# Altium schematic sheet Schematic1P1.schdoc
size 555 x 555 mm; Symbol: Drawing-Symbol_A4; Company: 嘉立创EDA; Version: V1.0; Page Size: A4; @Project Name: psone; @Update Date: 2026-04-22; @Create Date: 2026-04-22; Device: Drawing-Symbol_A4; @Board Name: Board1; @Page Name: P1; @Create Time: 20:13:25; @Page Count: 1; @Page No: 1; @Schematic Name: Schematic1; @Update Time: 20:13:25; @Assembly Variant: Basic; Border: 1; Title Block Position: 3; Size: A4; Width: 2185.03937007874; Height: 2185.03937007874; Region Start: 1; X Region Count: 6; Y Region Count: 4; Blade Width: 10
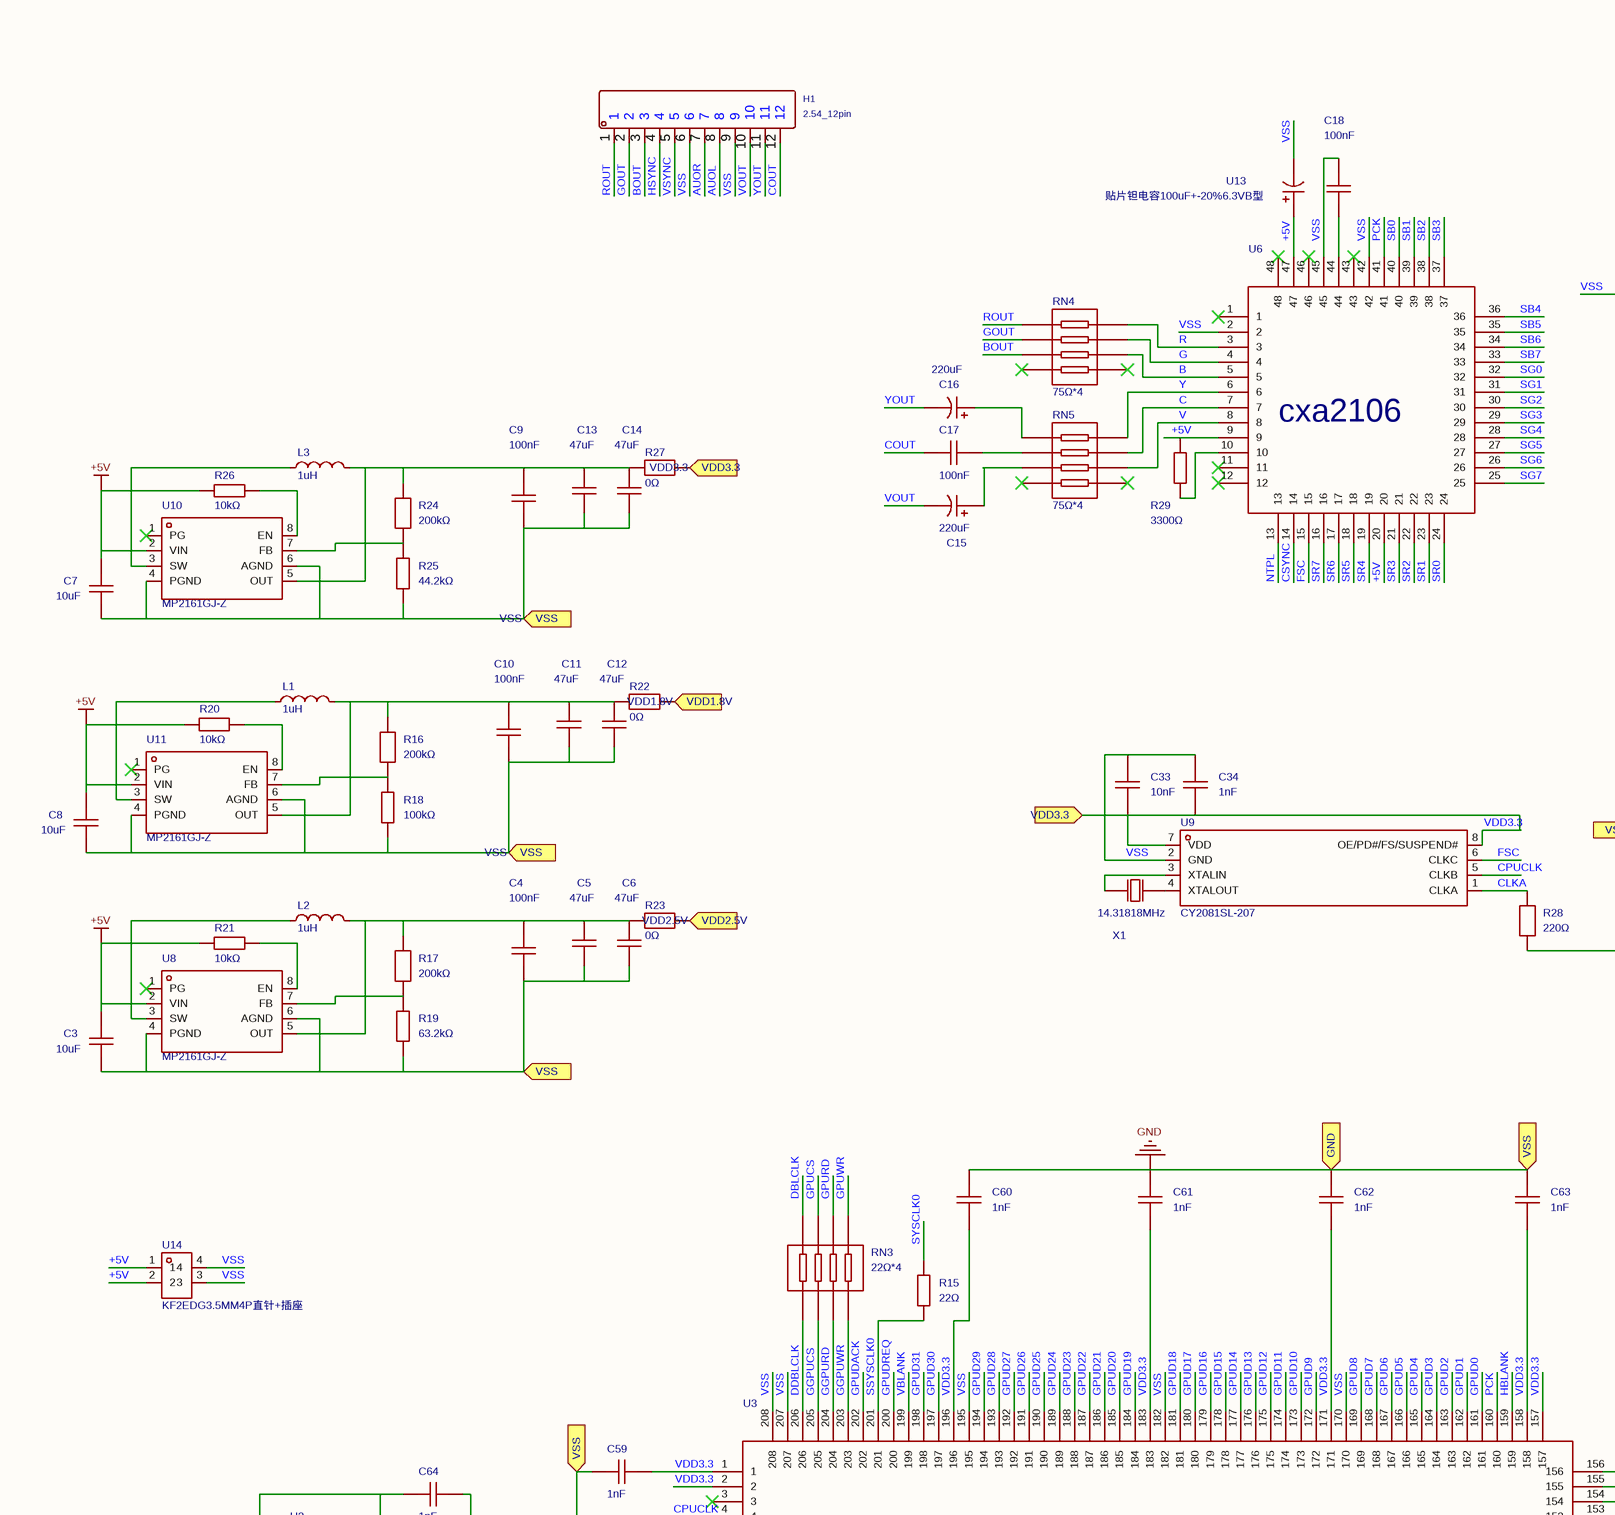
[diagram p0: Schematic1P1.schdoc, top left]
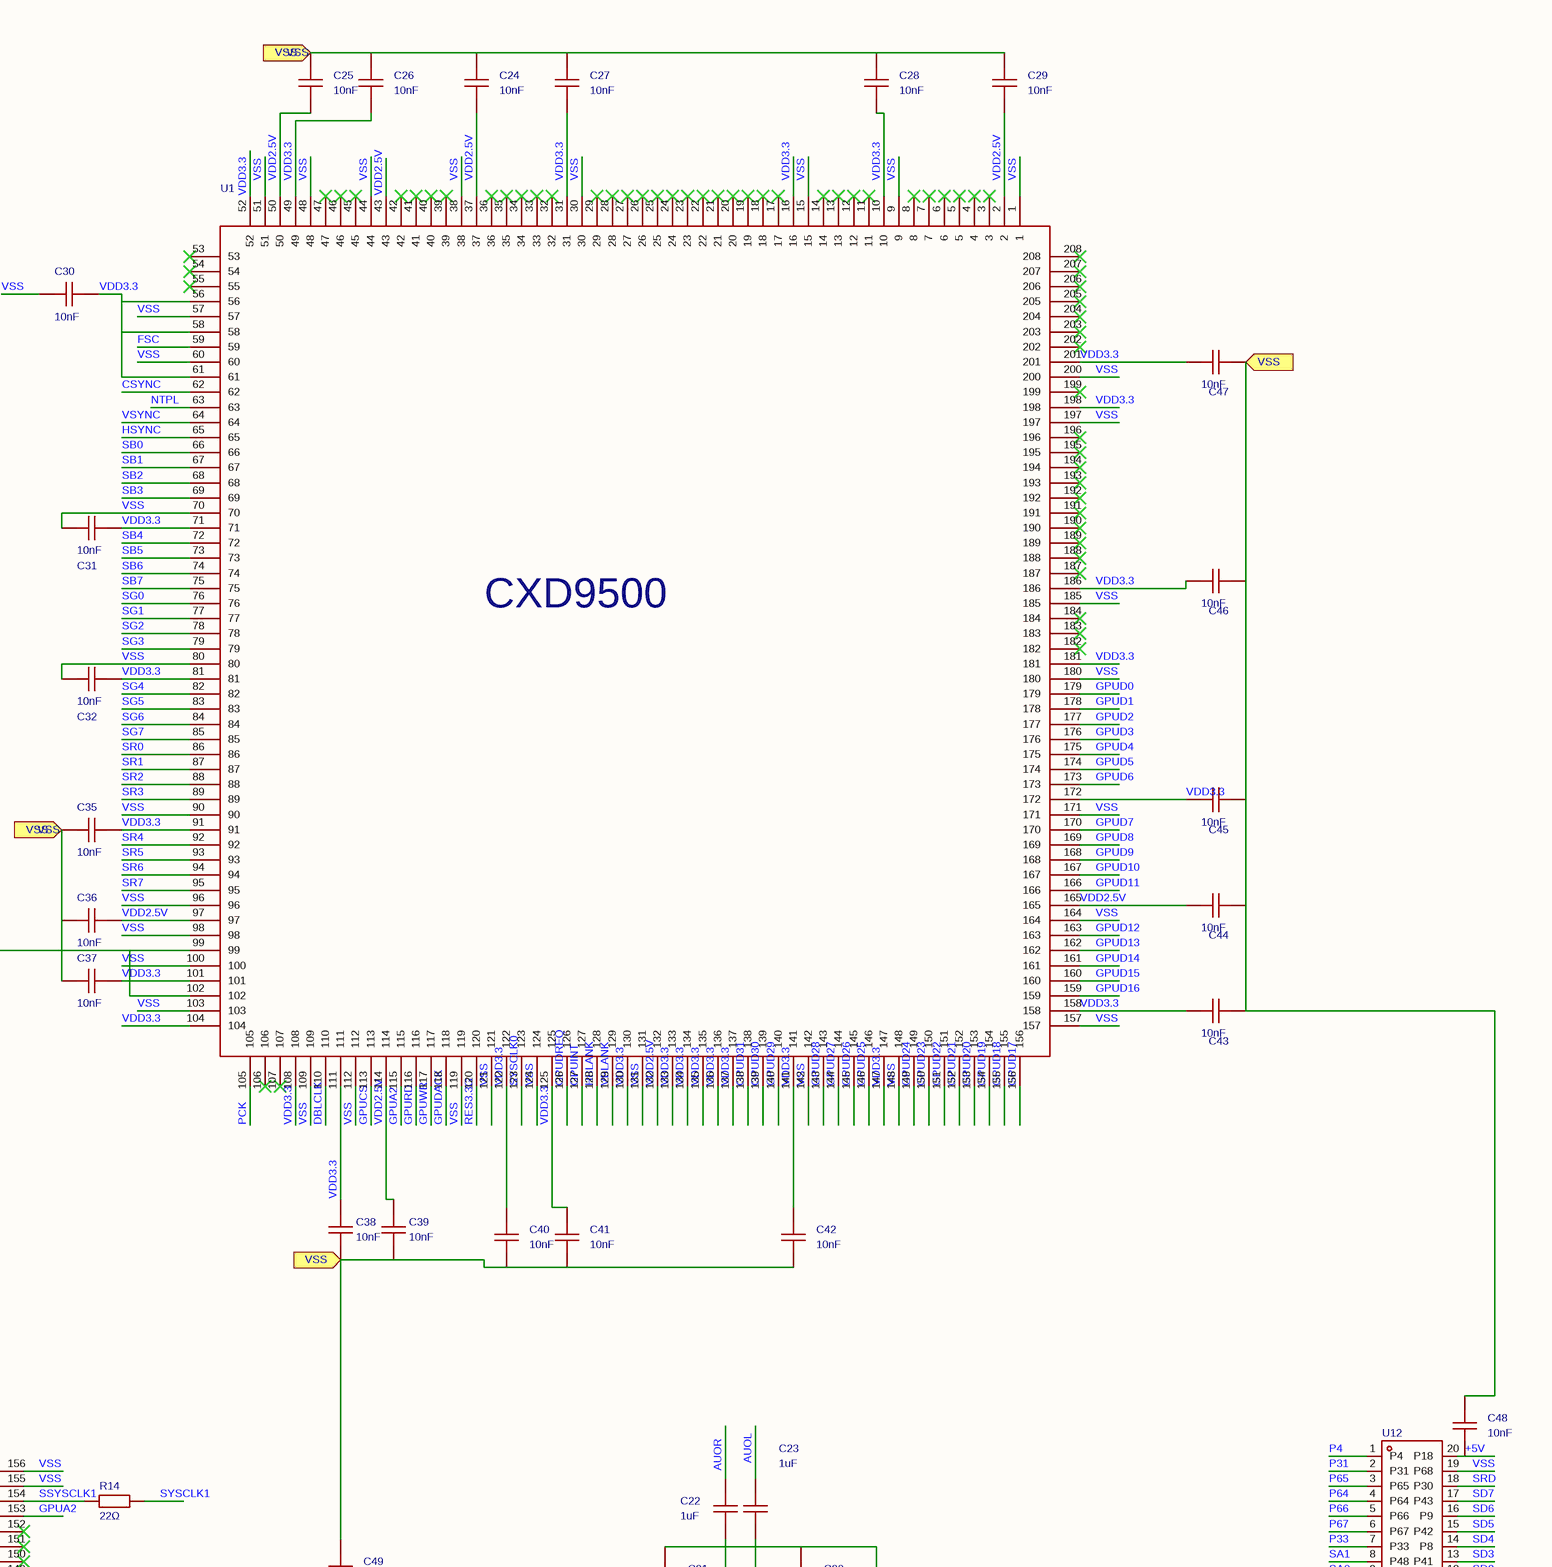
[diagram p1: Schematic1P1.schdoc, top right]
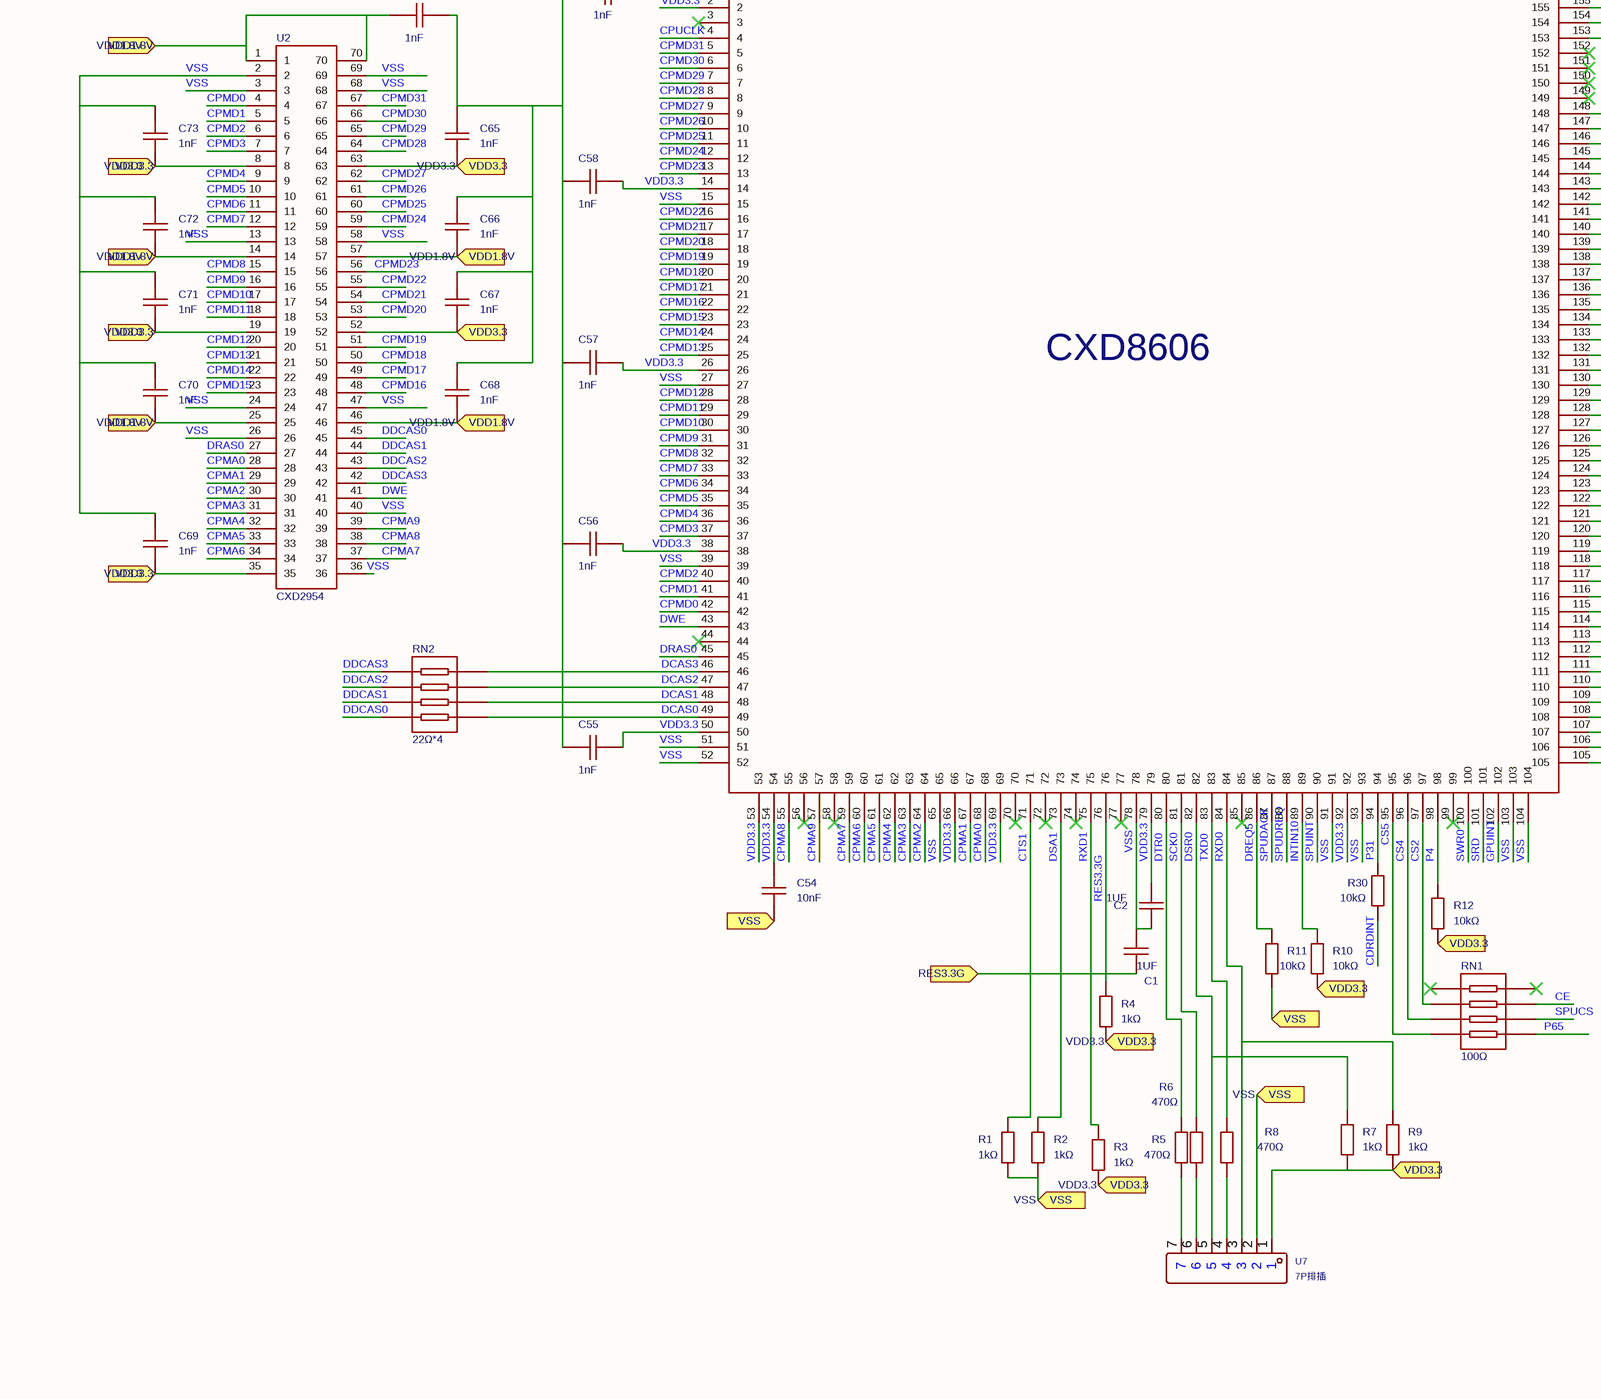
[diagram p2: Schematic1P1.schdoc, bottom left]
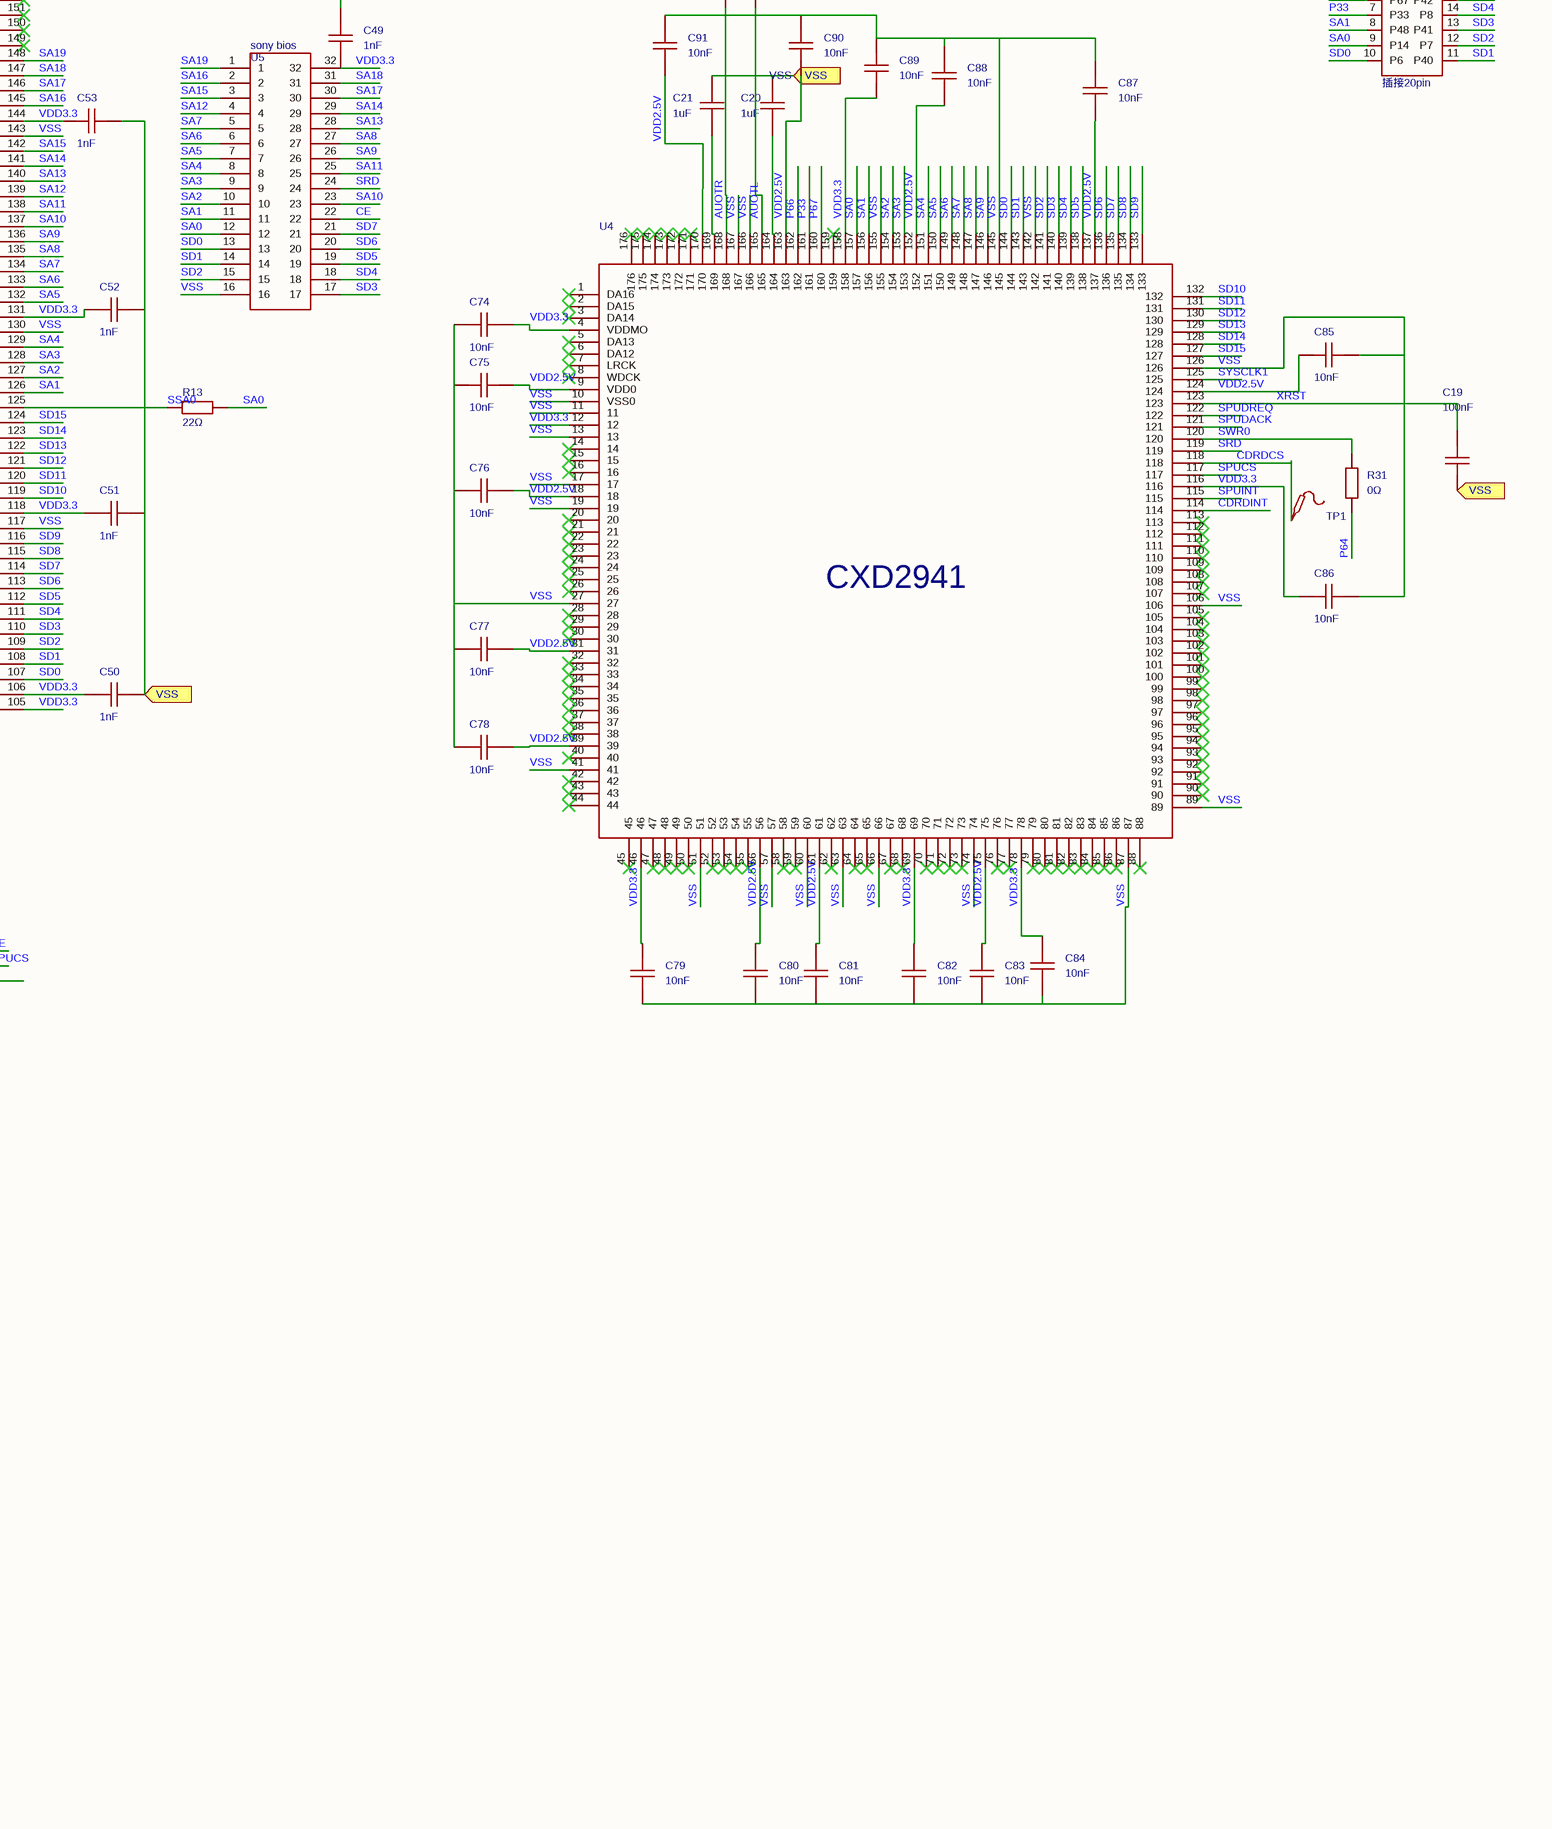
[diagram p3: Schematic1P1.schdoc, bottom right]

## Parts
C1  1UF  [C0603]
C2  1UF  [C0603]
C3  10uF  [C0603]
C4  100nF  [C0805]
C5  47uF  [C0805]
C6  47uF  [C0805]
C7  10uF  [C0603]
C8  10uF  [C0603]
C9  100nF  [C0805]
C10  100nF  [C0805]
C11  47uF  [C0805]
C12  47uF  [C0805]
C13  47uF  [C0805]
C14  47uF  [C0805]
C15  220uF  [CAP-SMD_L3.5-W2.8-R-RD]
C16  220uF  [CAP-SMD_L3.5-W2.8-R-RD]
C17  100nF  [C0805]
C18  100nF  [C0805]
C19  100nF  [C0805]
C20  1uF  [C0805]
C21  1uF  [C0805]
C22  1uF  [C0805]
C23  1uF  [C0805]
C24  10nF  [C0603]
C25  10nF  [C0603]
C26  10nF  [C0603]
C27  10nF  [C0603]
C28  10nF  [C0603]
C29  10nF  [C0603]
C30  10nF  [C0603]
C31  10nF  [C0603]
C32  10nF  [C0603]
C33  10nF  [C0603]
C34  1nF  [C0603]
C35  10nF  [C0603]
C36  10nF  [C0603]
C37  10nF  [C0603]
C38  10nF  [C0603]
C39  10nF  [C0603]
C40  10nF  [C0603]
C41  10nF  [C0603]
C42  10nF  [C0603]
C43  10nF  [C0603]
C44  10nF  [C0603]
C45  10nF  [C0603]
C46  10nF  [C0603]
C47  10nF  [C0603]
C48  10nF  [C0603]
C49  1nF  [C0603]
C50  1nF  [C0603]
C51  1nF  [C0603]
C52  1nF  [C0603]
C53  1nF  [C0603]
C54  10nF  [C0603]
C55  1nF  [C0603]
C56  1nF  [C0603]
C57  1nF  [C0603]
C58  1nF  [C0603]
C59  1nF  [C0603]
C60  1nF  [C0603]
C61  1nF  [C0603]
C62  1nF  [C0603]
C63  1nF  [C0603]
C64  1nF  [C0603]
C65  1nF  [C0603]
C66  1nF  [C0603]
C67  1nF  [C0603]
C68  1nF  [C0603]
C69  1nF  [C0603]
C70  1nF  [C0603]
C71  1nF  [C0603]
C72  1nF  [C0603]
C73  1nF  [C0603]
C74  10nF  [C0603]
C75  10nF  [C0603]
C76  10nF  [C0603]
C77  10nF  [C0603]
C78  10nF  [C0603]
C79  10nF  [C0603]
C80  10nF  [C0603]
C81  10nF  [C0603]
C82  10nF  [C0603]
C83  10nF  [C0603]
C84  10nF  [C0603]
C85  10nF  [C0603]
C86  10nF  [C0603]
C87  10nF  [C0603]
C88  10nF  [C0603]
C89  10nF  [C0603]
C90  10nF  [C0603]
C91  10nF  [C0603]
H1  2.54_12pin  [12PIN-P2.54]
L1  1uH  [IND-SMD_L3.0-W3.0_LPS3015-222ML]
L2  1uH  [IND-SMD_L3.0-W3.0_LPS3015-222ML]
L3  1uH  [IND-SMD_L3.0-W3.0_LPS3015-222ML]
R1  1kΩ  [R0603]
R2  1kΩ  [R0603]
R3  1kΩ  [R0603]
R4  1kΩ  [R0603]
R5  470Ω  [R0603]
R6  470Ω  [R0603]
R7  1kΩ  [R0603]
R8  470Ω  [R0603]
R9  1kΩ  [R0603]
R10  10kΩ  [R0603]
R11  10kΩ  [R0603]
R12  10kΩ  [R0603]
R13  22Ω  [R0603]
R14  22Ω  [R0603]
R15  22Ω  [R0603]
R16  200kΩ  [R0805]
R17  200kΩ  [R0805]
R18  100kΩ  [R0805]
R19  63.2kΩ  [R0805]
R20  10kΩ  [R0805]
R21  10kΩ  [R0805]
R22  0Ω  [R1206]
R23  0Ω  [R1206]
R24  200kΩ  [R0805]
R25  44.2kΩ  [R0805]
R26  10kΩ  [R0805]
R27  0Ω  [R1206]
R28  220Ω  [R0805]
R29  3300Ω  [R0603]
R30  10kΩ  [R0603]
R31  0Ω  [R0603]
RN1  100Ω  [RES-ARRAY-SMD_0603-8P-L3.2-W1.6-BL]
RN2  22Ω*4  [RES-ARRAY-SMD_0603-8P-L3.2-W1.6-BL]
RN3  22Ω*4  [RES-ARRAY-SMD_0603-8P-L3.2-W1.6-BL]
RN4  75Ω*4  [RES-ARRAY-SMD_0603-8P-L3.2-W1.6-BL]
RN5  75Ω*4  [RES-ARRAY-SMD_0603-8P-L3.2-W1.6-BL]
TP1  (no value)  [Test-Point-0.5mm]
U1  (no value)  [PQFP-208_L28.0-W28.0-P0.50-LS31.2-BL]
U2  CXD2954  [tssop-70]
U3  (no value)  [PQFP-208_L28.0-W28.0-P0.50-LS31.2-BL]
U4  (no value)  [LQFP-176_24.0X24.0X0.5P]
U5  (no value)  [628128SMD]
U6  (no value)  [ADV7123KSTZ50]
U7  7P排插  [7P排插]
U8  MP2161GJ-Z  [TSOT-23-8_L2.9-W1.6-P0.65-LS2.8-BR]
U9  CY2081SL-207  [SOIC-8_L4.9-W3.9-P1.27-LS6.0-BL]
U10  MP2161GJ-Z  [TSOT-23-8_L2.9-W1.6-P0.65-LS2.8-BR]
U11  MP2161GJ-Z  [TSOT-23-8_L2.9-W1.6-P0.65-LS2.8-BR]
U12  插接20pin  [20PIN-2.0MM_2_10]
U13  贴片钽电容100uF+-20%6.3VB型  [CAP-SMD_L3.5-W2.8-FD]
U14  KF2EDG3.5MM4P直针+插座  [CONN-TH_4P-P3.50_KF2EDGV-3.5-4P-1]
X1  14.31818MHz  [HC-49S_L11.4-W4.8-LS12.7]

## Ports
GND (in), RES3.3G (in), VDD1.8V (in), VDD2.5V (in), VDD3.3 (in), VSS (in)

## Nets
+5V: C3.2 C7.2 C8.2 C48.2 R20.2 R21.2 R26.2 R29.1 U6.9 U6.20 U6.47 U8.2(VIN) U10.2(VIN) U11.2(VIN) U12.20(P18) U13.1 U14.1 U14.2
VSS: C1.2 C2.1 C3.1 C4.1 C5.1 C6.1 C7.1 C8.1 C9.1 C10.1 C11.1 C12.1 C13.1 C14.1 C18.2 C19.1 C20.2 C21.2 C24.2 C25.2 C26.2 C27.2 C28.2 C29.2 C30.2 C31.2 C32.2 C33.2 C34.2 C35.2 C36.2 C37.2 C38.1 C39.1 C40.1 C41.1 C42.1 C43.1 C44.1 C45.1 C46.1 C47.1 C48.1 C49.2 C50.2 C51.2 C52.2 C53.2 C54.2 C55.1 C56.1 C57.1 C58.1 C59.1 C60.2 C61.2 C62.2 C63.2 C64.2 C65.2 C66.2 C67.2 C68.2 C69.2 C70.2 C71.2 C72.2 C73.2 C74.1 C75.1 C76.1 C77.1 C78.1 C79.1 C80.1 C81.1 C82.1 C83.1 C84.1 C85.1 C86.1 C87.1 C88.1 C89.1 C90.1 C91.1 H1.6 H1.9 R1.1 R2.1 R11.1 R18.1 R19.1 R25.1 U1.1 U1.9 U1.15 U1.30 U1.38 U1.44 U1.48 U1.51 U1.57 U1.60 U1.70 U1.80 U1.90 U1.96 U1.98 U1.100 U1.103 U1.109 U1.112 U1.119 U1.121 U1.124 U1.131 U1.142 U1.148 U1.157 U1.164 U1.171 U1.180 U1.185 U1.197 U1.200 U2.2 U2.3 U2.13 U2.24 U2.26 U2.36 U2.40 U2.47 U2.58 U2.68 U2.69 U3.15 U3.27 U3.39 U3.51 U3.52 U3.65 U3.78 U3.91 U3.93 U3.103 U3.104 U3.117 U3.130 U3.143 U3.155 U3.156 U3.170 U3.182 U3.195 U3.207 U3.208 U4.10(VSS0) U4.11 U4.13 U4.17 U4.19 U4.27 U4.41 U4.51 U4.57 U4.60 U4.63 U4.66 U4.74 U4.87 U4.89 U4.106 U4.126 U4.142 U4.145 U4.155 U4.166 U4.167 U5.16 U6.2 U6.42 U6.45 U7.2 U8.4(PGND) U8.6(AGND) U9.2(GND) U10.4(PGND) U10.6(AGND) U11.4(PGND) U11.6(AGND) U12.19(P68) U13.2 U14.3 U14.4 ; port VSS, port GND  [also labelled GND]
AUOL: C23.2 H1.8
AUOR: C22.2 H1.7
AUOTL: C23.1 U4.165
AUOTR: C22.1 U4.168
B: RN4.6 U6.5
BOUT: H1.3 RN4.3
C: RN5.7 U6.7
CDRDCS: TP1.1 U4.118
CDRDINT: R30.1 U4.114
CE: RN1.7 U5.22
CLKA: R28.2 U9.1(CLKA)
COUT: C17.2 H1.12
CPMA0: U2.28 U3.68
CPMA1: U2.29 U3.67
CPMA2: U2.30 U3.64
CPMA3: U2.31 U3.63
CPMA4: U2.32 U3.62
CPMA5: U2.33 U3.61
CPMA6: U2.34 U3.60
CPMA7: U2.37 U3.59
CPMA8: U2.38 U3.55
CPMA9: U2.39 U3.57
CPMD0: U2.4 U3.42
CPMD1: U2.5 U3.41
CPMD2: U2.6 U3.40
CPMD3: U2.7 U3.37
CPMD4: U2.9 U3.36
CPMD5: U2.10 U3.35
CPMD6: U2.11 U3.34
CPMD7: U2.12 U3.33
CPMD8: U2.15 U3.32
CPMD9: U2.16 U3.31
CPMD10: U2.17 U3.30
CPMD11: U2.18 U3.29
CPMD12: U2.20 U3.28
CPMD13: U2.21 U3.25
CPMD14: U2.22 U3.24
CPMD15: U2.23 U3.23
CPMD16: U2.48 U3.22
CPMD17: U2.49 U3.21
CPMD18: U2.50 U3.20
CPMD19: U2.51 U3.19
CPMD20: U2.53 U3.18
CPMD21: U2.54 U3.17
CPMD22: U2.55 U3.16
CPMD23: U2.56 U3.13
CPMD24: U2.59 U3.12
CPMD25: U2.60 U3.11
CPMD26: U2.61 U3.10
CPMD27: U2.62 U3.9
CPMD28: U2.64 U3.8
CPMD29: U2.65 U3.7
CPMD30: U2.66 U3.6
CPMD31: U2.67 U3.5
CPUCLK: U3.4 U9.5(CLKB)
CS2: RN1.2 U3.97
CS4: RN1.3 U3.96
CS5: RN1.4 U3.95
CSYNC: U1.62 U6.14
CTS1: R1.2 U3.71
DBLCLK: RN3.8 U1.110
DCAS0: RN2.5 U3.49
DCAS1: RN2.6 U3.48
DCAS2: RN2.7 U3.47
DCAS3: RN2.8 U3.46
DDBLCLK: RN3.1 U3.206
DDCAS0: RN2.4 U2.45
DDCAS1: RN2.3 U2.44
DDCAS2: RN2.2 U2.43
DDCAS3: RN2.1 U2.42
DRAS0: U2.27 U3.45
DREQ5: R11.2 U3.86
DSA1: R2.2 U3.73
DSR0: R7.2 U3.82 U7.5
DTR0: R5.2 U3.80
DWE: U2.41 U3.43
FSC: U1.59 U6.15 U9.6(CLKC)
G: RN4.7 U6.4
GGPUCS: RN3.2 U3.205
GGPURD: RN3.3 U3.204
GGPUWR: RN3.4 U3.203
GOUT: H1.2 RN4.2
GPUA2: U1.115 U3.153
GPUCS: RN3.7 U1.113
GPUD0: U1.179 U3.161
GPUD1: U1.178 U3.162
GPUD2: U1.177 U3.163
GPUD3: U1.176 U3.164
GPUD4: U1.175 U3.165
GPUD5: U1.174 U3.166
GPUD6: U1.173 U3.167
GPUD7: U1.170 U3.168
GPUD8: U1.169 U3.169
GPUD9: U1.168 U3.172
GPUD10: U1.167 U3.173
GPUD11: U1.166 U3.174
GPUD12: U1.163 U3.175
GPUD13: U1.162 U3.176
GPUD14: U1.161 U3.177
GPUD15: U1.160 U3.178
GPUD16: U1.159 U3.179
GPUD17: U1.156 U3.180
GPUD18: U1.155 U3.181
GPUD19: U1.154 U3.184
GPUD20: U1.153 U3.185
GPUD21: U1.152 U3.186
GPUD22: U1.151 U3.187
GPUD23: U1.150 U3.188
GPUD24: U1.149 U3.189
GPUD25: U1.146 U3.190
GPUD26: U1.145 U3.191
GPUD27: U1.144 U3.192
GPUD28: U1.143 U3.193
GPUD29: U1.140 U3.194
GPUD30: U1.139 U3.197
GPUD31: U1.138 U3.198
GPUDACK: U1.118 U3.202
GPUDREQ: U1.126 U3.200
GPUINT: U1.127 U3.102
GPURD: RN3.6 U1.116
GPUWR: RN3.5 U1.117
HBLANK: U1.128 U3.159
HSYNC: H1.4 U1.65
INTIN10: R10.2 U3.89
NTPL: U1.63 U6.13
P4: R12.2 U3.98 U12.1(P4)
P31: R30.2 U3.94 U12.2(P31)
P33: U4.161 U12.7(P33)
P64: R31.2 U12.4(P64)
P65: RN1.5 U12.3(P65)
P66: U4.162 U12.5(P66)
P67: U4.160 U12.6(P67)
PCK: U1.105 U3.160 U6.41
R: RN4.8 U6.3
RES3.3G: C1.1 R4.2 U1.120 U3.76 ; port RES3.3G
ROUT: H1.1 RN4.1
RXD0: R9.2 U3.84 U7.3
RXD1: R3.2 U3.75
SA0: R13.1 U4.157 U5.12 U12.9(P14)
SA1: U3.126 U4.156 U5.11 U12.8(P48)
SA2: U3.127 U4.154 U5.10
SA3: U3.128 U4.153 U5.9
SA4: U3.129 U4.151 U5.8
SA5: U3.132 U4.150 U5.7
SA6: U3.133 U4.149 U5.6
SA7: U3.134 U4.148 U5.5
SA8: U3.135 U4.147 U5.27
SA9: U3.136 U4.146 U5.26
SA10: U3.137 U5.23
SA11: U3.138 U5.25
SA12: U3.139 U5.4
SA13: U3.140 U5.28
SA14: U3.141 U5.29
SA15: U3.142 U5.3
SA16: U3.145 U5.2
SA17: U3.146 U5.30
SA18: U3.147 U5.31
SA19: U3.148 U5.1
SB0: U1.66 U6.40
SB1: U1.67 U6.39
SB2: U1.68 U6.38
SB3: U1.69 U6.37
SB4: U1.72 U6.36
SB5: U1.73 U6.35
SB6: U1.74 U6.34
SB7: U1.75 U6.33
SCK0: R6.2 U3.81
SD0: U3.107 U4.144 U5.13 U12.10(P6)
SD1: U3.108 U4.143 U5.14 U12.11(P40)
SD2: U3.109 U4.141 U5.15 U12.12(P7)
SD3: U3.110 U4.140 U5.17 U12.13(P41)
SD4: U3.111 U4.139 U5.18 U12.14(P8)
SD5: U3.112 U4.138 U5.19 U12.15(P42)
SD6: U3.113 U4.136 U5.20 U12.16(P9)
SD7: U3.114 U4.135 U5.21 U12.17(P43)
SD8: U3.115 U4.134
SD9: U3.116 U4.133
SD10: U3.119 U4.132
SD11: U3.120 U4.131
SD12: U3.121 U4.130
SD13: U3.122 U4.129
SD14: U3.123 U4.128
SD15: U3.124 U4.127
SG0: U1.76 U6.32
SG1: U1.77 U6.31
SG2: U1.78 U6.30
SG3: U1.79 U6.29
SG4: U1.82 U6.28
SG5: U1.83 U6.27
SG6: U1.84 U6.26
SG7: U1.85 U6.25
SPUCS: RN1.6 U4.117
SPUDACK: U3.87 U4.121
SPUDREQ: U3.88 U4.122
SPUINT: U3.90 U4.115
SR0: U1.86 U6.24
SR1: U1.87 U6.23
SR2: U1.88 U6.22
SR3: U1.89 U6.21
SR4: U1.92 U6.19
SR5: U1.93 U6.18
SR6: U1.94 U6.17
SR7: U1.95 U6.16
SRD: U3.101 U4.119 U5.24 U12.18(P30)
SSA0: R13.2 U3.125
SSYSCLK0: R15.2 U3.201
SSYSCLK1: R14.2 U3.154
SWR0: R31.1 U3.100 U4.120
SYSCLK0: R15.1 U1.123
SYSCLK1: R14.1 U4.125
TXD0: R8.2 U3.83
V: RN5.6 U6.8
VBLANK: U1.129 U3.199
VDD1.8V: C64.1 C66.1 C68.1 C70.1 C72.1 R22.2 U2.1 U2.14 U2.25 U2.46 U2.57 U2.70 ; port VDD1.8V
VDD2.5V: C24.1 C25.1 C29.1 C36.1 C39.2 C44.2 C75.2 C76.2 C77.2 C78.2 C80.2 C81.2 C83.2 C85.2 C87.2 C88.2 C90.2 C91.2 R23.2 U1.2 U1.37 U1.43 U1.50 U1.97 U1.114 U1.132 U1.165 U4.9(VDD0) U4.18 U4.31 U4.39 U4.56 U4.61 U4.75 U4.124 U4.137 U4.152 U4.163 U4.170 ; port VDD2.5V
VDD3.3: C2.2 C26.1 C27.1 C28.1 C30.1 C31.1 C32.1 C33.1 C34.1 C35.1 C37.1 C38.2 C40.2 C41.2 C42.2 C43.2 C45.2 C46.2 C47.2 C49.1 C50.1 C51.1 C52.1 C53.1 C54.1 C55.2 C56.2 C57.2 C58.2 C59.2 C60.1 C61.1 C62.1 C63.1 C65.1 C67.1 C69.1 C71.1 C73.1 C74.2 C79.2 C82.2 C84.2 C86.2 C89.2 R3.1 R4.1 R7.1 R9.1 R10.1 R12.1 R27.2 U1.10 U1.16 U1.31 U1.49 U1.52 U1.56 U1.58 U1.61 U1.71 U1.81 U1.91 U1.101 U1.104 U1.108 U1.111 U1.122 U1.125 U1.130 U1.133 U1.134 U1.135 U1.136 U1.137 U1.141 U1.147 U1.158 U1.172 U1.181 U1.186 U1.198 U1.201 U2.8 U2.19 U2.35 U2.52 U2.63 U3.1 U3.2 U3.14 U3.26 U3.38 U3.50 U3.53 U3.54 U3.66 U3.69 U3.79 U3.92 U3.105 U3.106 U3.118 U3.131 U3.144 U3.157 U3.158 U3.171 U3.183 U3.196 U4.4(VDDMO) U4.12 U4.46 U4.69 U4.78 U4.116 U4.158 U5.32 U7.1 U9.7(VDD) U9.8(OE/PD#/FS/SUSPEND#) ; port VDD3.3
VOUT: C15.2 H1.10
VSYNC: H1.5 U1.64
XRST: C19.2 U4.123
Y: RN5.8 U6.6
YOUT: C16.2 H1.11
NetC4_2: C4.2 C5.2 C6.2 L2.2 R17.2 R23.1 U8.5(OUT)
NetC9_2: C9.2 C13.2 C14.2 L3.2 R24.2 R27.1 U10.5(OUT)
NetC10_2: C10.2 C11.2 C12.2 L1.2 R16.2 R22.1 U11.5(OUT)
NetC15_1: C15.1 RN5.3
NetC16_1: C16.1 RN5.1
NetC17_1: C17.1 RN5.2
NetC18_1: C18.1 U6.44
NetC20_1: C20.1 U4.164
NetC21_1: C21.1 U4.169
NetL1_1: L1.1 U11.3(SW)
NetL2_1: L2.1 U8.3(SW)
NetL3_1: L3.1 U10.3(SW)
NetR5_1: R5.1 U7.7
NetR6_1: R6.1 U7.6
NetR8_1: R8.1 U7.4
NetR16_1: R16.1 R18.2 U11.7(FB)
NetR17_1: R17.1 R19.2 U8.7(FB)
NetR20_1: R20.1 U11.8(EN)
NetR21_1: R21.1 U8.8(EN)
NetR24_1: R24.1 R25.2 U10.7(FB)
NetR26_1: R26.1 U10.8(EN)
NetR28_1: R28.1 U1.99 U1.102
NetR29_2: R29.2 U6.10
NetU9_3: U9.3(XTALIN) X1.1(OSC1)
NetU9_4: U9.4(XTALOUT) X1.2(OSC2)

Not connected (* = marked no-connect by the designer): RN1 1* 8*; RN4 4* 5*; RN5 4* 5*; U1 3* 4* 5* 6* 7* 8* 11* 12* 13* 14* 17* 18* 19* 20* 21* 22* 23* 24* 25* 26* 27* 28* 29* 32* 33* 34* 35* 36* 39* 40* 41* 42* 45* 46* 47* 53* 54* 55* 106* 107* 182* 183* 184* 187* 188* 189* 190* 191* 192* 193* 194* 195* 196* 199* 202* 203* 204* 205* 206* 207* 208*; U3 3* 44* 56* 58* 70* 72* 74* 77* 85* 99* 149* 150* 151* 152*; U4 1(DA16)* 2(DA15)* 3(DA14)* 5(DA13)* 6(DA12)* 7(LRCK)* 8(WDCK)* 14* 15* 16* 20* 21* 22* 23* 24* 25* 26* 28* 29* 30* 32* 33* 34* 35* 36* 37* 38* 40* 42* 43* 44* 45* 47* 48* 49* 50* 52* 53* 54* 55* 58* 59* 62* 64* 65* 67* 68* 70* 71* 72* 73* 76* 77* 79* 80* 81* 82* 83* 84* 85* 86* 88* 90* 91* 92* 93* 94* 95* 96* 97* 98* 99* 100* 101* 102* 103* 104* 105* 107* 108* 109* 110* 111* 112* 113* 159* 171* 172* 173* 174* 175* 176*; U6 1* 11* 12* 43* 46* 48*; U8 1(PG)*; U10 1(PG)*; U11 1(PG)*

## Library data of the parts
C1 C2 = C0603_1uf: 容值:1uF;精度:±10%;额定电压:50V;温度系数:X5R;; Manufacturer: SAMSUNG(三星); ManufacturerPart: CL10A105KB8NNNC; AddInBom: yes; ModelId: ac125912035d415993ca9572d50418b135cfefd17b8941a1ab3af5e4210788bd; ModelName: C0603_L1.6-W0.8-H0.8; ModelTransform: 62.992,31.496,0,0,0,0,0,0,0; Tolerance: ±10%; Voltage Rated: 50V; Temperature Coefficient: X5R
C3 C7 C8 = CL10A106KP8NNNC: 容值:10uF;精度:±10%;额定电压:10V;温度系数:X5R;; Manufacturer: SAMSUNG(三星); AddInBom: yes; ModelId: ac125912035d415993ca9572d50418b10819f05c4eef4c71ace90d822a990e87; ModelName: C0603_L1.6-W0.8-H0.8; ModelTransform: 62.992,31.496,0,0,0,0,0,0,0; Tolerance: ±10%; Voltage Rating: 10V; Temperature Coefficient: X5R
C4 C9 C10 C17-C21 = CC0805KRX7R9BB104: 容值:100nF;精度:±10%;额定电压:50V;温度系数:X7R;; Manufacturer: YAGEO(国巨); AddInBom: yes; ModelId: 1ba041120af144c991958decab20d2410819f05c4eef4c71ace90d822a990e87; ModelName: C0805_L2.0-W1.3-H1.3; ModelTransform: 78.74,51.181,0,0,0,0,0,0.0005,0; Tolerance: ±10%; Voltage Rating: 50V; Temperature Coefficient: X7R
C5 C6 C11-C14 = CL21A476MQYNNNE: 容值:47uF;精度:±20%;额定电压:6.3V;温度系数:X5R;; Manufacturer: SAMSUNG(三星); AddInBom: yes; ModelId: 1ba041120af144c991958decab20d2410819f05c4eef4c71ace90d822a990e87; ModelName: C0805_L2.0-W1.3-H1.3; ModelTransform: 78.74,51.181,0,0,0,0,0,0.0005,0; Tolerance: ±20%; Voltage Rating: 6.3V; Temperature Coefficient: X5R
C15 C16 = F930J227KBA: 容值:220uF;精度:±10%;额定电压:6.3V;等效串联电阻(ESR):1.2Ω@100kHz;; Manufacturer: Kyocera AVX; AddInBom: yes; ModelId: 0dfcda272f9b43668c6086d3a08712ba0819f05c4eef4c71ace90d822a990e87; ModelName: CASE-B_L3.5-W2.8-H1.9; ModelTransform: 145.669,110.236,0,180,0,0,0,0,0; Tolerance: ±10%; Voltage Rating: 6.3V
C22 C23 = CC0805KRX7R9BB104: 容值:100nF;精度:±10%;额定电压:50V;温度系数:X7R;; Manufacturer: YAGEO(国巨); 3D Model: 1ba041120af144c991958decab20d2410819f05c4eef4c71ace90d822a990e87; 3D Model Transform: 78.74,51.181,0,0,0,0,0,0.0005,0; Tolerance: ±10%; Voltage Rating: 50V; Temperature Coefficient: X7R; AddInBom: yes; ModelName: C0805_L2.0-W1.3-H1.3
C24-C48 C54 C74-C91 = GRM1887U1H103JA01D: 容值:10nF;精度:±5%;额定电压:50V;温度系数:U2J;; Manufacturer: muRata(村田); AddInBom: yes; ModelId: ac125912035d415993ca9572d50418b10819f05c4eef4c71ace90d822a990e87; ModelName: C0603_L1.6-W0.8-H0.8; ModelTransform: 62.992,31.496,0,0,0,0,0,0,0; Tolerance: ±5%; Voltage Rating: 50V; Temperature Coefficient: U2J
C49-C53 C55-C73 = C1608X7R1H102M: 容值:1nF;精度:±20%;额定电压:50V;温度系数:X7R;; Manufacturer: TDK; AddInBom: yes; ModelId: ac125912035d415993ca9572d50418b10819f05c4eef4c71ace90d822a990e87; ModelName: C0603_L1.6-W0.8-H0.8; ModelTransform: 62.992,31.496,0,0,0,0,0,0,0; Tolerance: ±20%; Voltage Rating: 50V; Temperature Coefficient: X7R
H1 = 2.54_12pin: ManufacturerPart: Headers  Pins2.54mm1*10P; Value: 12PIN
L1-L3 = LPS3015-102MRC: 电感值:1uH;精度:±20%;额定电流:2A;饱和电流(Isat):2.5A;类型:磁胶屏蔽电感;; Manufacturer: Coilcraft(线艺); AddInBom: yes; ModelId: 178cdbd8750f46e4bc57312d64f3b63c0819f05c4eef4c71ace90d822a990e87; ModelTransform: 116.1415,116.1415,0,0,0,0,0,0,0; Tolerance: ±20%; Current Rating: 2A; Current - Saturation(Isat): 2.5A; DC Resistance(DCR): 75mΩ; Type: 磁胶屏蔽电感
R1-R4 R7 R9 R13-R15 R29 = 1k 0603: 电阻类型:厚膜电阻;阻值:1kΩ;精度:±1%;功率:100mW;温度系数:±100ppm/℃;最大工作电压:75V;工作温度范围:-55℃~+155℃;; Manufacturer: UNI-ROYAL(厚声); Symbol: 0603WAF1001T5E; AddInBom: yes; ModelId: 3281a289d46d4bb1877be1eabd090e136c1edf6a8c084a3a8b045355d8cfbf0c; ModelName: R0603_L1.6-W0.8-H0.8; ModelTransform: 62.992,31.496,0,0,0,0,0,0,0; Tolerance: ±1%; Power(Watts): 100mW; Overload Voltage (Max): 75V
R5 R6 R8 = 0603WAF4700T5E: 电阻类型:厚膜电阻;阻值:470Ω;精度:±1%;功率:100mW;工作电压:75V;温度系数:±100ppm/℃;; Manufacturer: UNI-ROYAL(厚声); AddInBom: yes; ModelId: fc143cca1e79419f9cd78b61e9279f080819f05c4eef4c71ace90d822a990e87; ModelTransform: 31.8897,63.7794,0,90,0,0,0,0,0; Tolerance: ±1%; Power(Watts): 100mW; Voltage-Supply(Max): 75V
R10-R12 = 0603WAF1002T5E: 电阻类型:厚膜电阻;阻值:10kΩ;精度:±1%;功率:100mW;工作电压:75V;温度系数:±100ppm/℃;; Manufacturer: UNI-ROYAL(厚声); AddInBom: yes; ModelId: fc143cca1e79419f9cd78b61e9279f080819f05c4eef4c71ace90d822a990e87; ModelTransform: 31.8897,63.7794,0,90,0,0,0,0,0; Tolerance: ±1%; Power(Watts): 100mW; Voltage-Supply(Max): 75V
R16 R17 R24 R28 = ESR10EZPF3163: 电阻类型:厚膜电阻;阻值:316kΩ;精度:±1%;功率:400mW;温度系数:±100ppm/℃;; Manufacturer: ROHM(罗姆); AddInBom: yes; ModelId: 37a81e68749a4138bd2dfa6897b24b850819f05c4eef4c71ace90d822a990e87; ModelName: R0805_L2.0-W1.3-H0.6; ModelTransform: 78.74,51.181,0,0,0,0,0,-0.0005,0; Tolerance: ±1%; Power(Watts): 400mW
R18-R21 R25 R26 = 0805W8F1003T5E: 电阻类型:厚膜电阻;阻值:100kΩ;精度:±1%;功率:125mW;工作电压:150V;温度系数:±100ppm/℃;; Manufacturer: UNI-ROYAL(厚声); Symbol: 0805W8F1003T5E_C149504; AddInBom: yes; ModelId: 37a81e68749a4138bd2dfa6897b24b850819f05c4eef4c71ace90d822a990e87; ModelName: R0805_L2.0-W1.3-H0.6; ModelTransform: 78.74,51.181,0,0,0,0,0,-0.0005,0; Tolerance: ±1%; Power(Watts): 125mW; Voltage-Supply(Max): 150V
R22 R23 R27 = CR1206F40000G: 电阻类型:厚膜电阻;阻值:0Ω;精度:±1%;功率:250mW;; Manufacturer: LIZ(丽智电子); AddInBom: yes; ModelId: 89a1f13db2384da588040e0b3c55bf660819f05c4eef4c71ace90d822a990e87; ModelName: R1206_L3.2-W1.6-H0.6; ModelTransform: 125.984,62.992,0,0,0,0,0,0,0; Tolerance: ±1%; Power(Watts): 250mW
R30 = 0603WAF1002T5E: 电阻类型:厚膜电阻;阻值:10kΩ;精度:±1%;功率:100mW;工作电压:75V;温度系数:±100ppm/℃;; Manufacturer: UNI-ROYAL(厚声); 3D Model: fc143cca1e79419f9cd78b61e9279f080819f05c4eef4c71ace90d822a990e87; 3D Model Transform: 31.8897,63.7794,0,90,0,0,0,0,0; Tolerance: ±1%; Power(Watts): 100mW; Voltage-Supply(Max): 75V; AddInBom: yes
R31 = 1k 0603: 电阻类型:厚膜电阻;阻值:1kΩ;精度:±1%;功率:100mW;温度系数:±100ppm/℃;最大工作电压:75V;工作温度范围:-55℃~+155℃;; Manufacturer: UNI-ROYAL(厚声); Symbol: 0603WAF1001T5E; 3D Model: 3281a289d46d4bb1877be1eabd090e136c1edf6a8c084a3a8b045355d8cfbf0c; 3D Model Transform: 62.992,31.496,0,0,0,0,0,0,0; Tolerance: ±1%; Power(Watts): 100mW; Overload Voltage (Max): 75V; AddInBom: yes; ModelName: R0603_L1.6-W0.8-H0.8
RN1 = 排阻: 电阻器数:4;阻值:1kΩ;精度:±5%;单个元件功率:62.5mW;温度系数:±200ppm/℃;; Manufacturer: UNI-ROYAL(厚声); Symbol: 4D03WGJ0102T5E; AddInBom: yes; ModelId: edf39f9a2dca4b9a94267f442dd4f95aef2d9f85bbab43d59d0f3682d1a2bd00; ModelName: R0603-8P_L3.2-W1.6-H0.6; ModelTransform: 125.984,62.992,0,0,0,0,0,0,0
RN2-RN5 = 0603*4_1: Symbol: 0603*4_C9900178091; AddInBom: yes; ModelId: edf39f9a2dca4b9a94267f442dd4f95a0819f05c4eef4c71ace90d822a990e87; ModelName: R0603-8P_L3.2-W1.6-H0.6; ModelTransform: 125.984,62.992,0,0,0,0,0,0,0
TP1 = Test-Point: Test Point 测试点; AddInBom: yes
U1 = CXD9500: Convert to PCB: yes; ModelId: 8cfdc8370b154462991ec26fa6bcc4890819f05c4eef4c71ace90d822a990e87; ModelName: PQFP-208_L28.0-W28.0-H3.8-P0.50-LS30.6-BL; ModelTransform: 1204.722015018463,1204.722015018463,149.60599577605723,0,0,0,0,0,0
U2 = cxd2954: AddInBom: yes; ModelId: 9c96f127935e423581bb111c8470c9550819f05c4eef4c71ace90d822a990e87; ModelName: tssop-70 sony; ModelTransform: 728.3449999999999,472.43999999999994,59.05499999999999,0,0,0,0,0,0
U3 = CXD8606: AddInBom: yes; ModelId: 8cfdc8370b154462991ec26fa6bcc4890819f05c4eef4c71ace90d822a990e87; ModelName: PQFP-208_L28.0-W28.0-H3.8-P0.50-LS30.6-BL; ModelTransform: 1204.722015018463,1204.722015018463,149.60599577605723,0,0,0,0,0,0
U4 = CXD2941: AddInBom: yes; ModelId: 906d956fdcf941199429b65641134ece0819f05c4eef4c71ace90d822a990e87; ModelName: LQFP-176_L24.0-W24.0-P0.50-LS26.0-TL-EP_ADI_SW-176-3; ModelTransform: 1023.6199999999999,1023.6199999999999,59.05499999999999,0,0,0,0,0,0
U5 = sony bios: AddInBom: yes
U6 = cxa2106: AddInBom: yes
U7 = 7P排插: Value: 7PIN
U8 U10 U11 = MP2161GJ-Z: 功能类型:降压型;工作电压:2.5V~6V;输出电压:-;输出电流:2A;输出类型:可调;; Manufacturer: MPS(芯源); AddInBom: yes; ModelId: a4a866e84c1d4e21a00dbb6d6e7ebbb60819f05c4eef4c71ace90d822a990e87; ModelTransform: 110.45568,114.173,0,180,0,0,0,0,0; Function: 降压型; Output Current: 2A; Frequency - Switching: 1.5MHz; Synchronous Rectifier: 否; Number of Outputs: 1; Topology: 降压式; Quiescent Current: 17uA; Switch tube (built-in/external): 内置; Output Type: 可调
U9 = CY2081SL-207: Manufacturer: Infineon/CYPRESS(赛普拉斯); AddInBom: yes; ModelId: e81d2f7d937b4a6ab1dca543ff5d56a40819f05c4eef4c71ace90d822a990e87; ModelName: SOIC-8_L4.9-W3.9-H1.7-LS6.0-P1.27; ModelTransform: 192.913,236.22,0,0,0,0,0,0,0
U12 = 20PIN2.0: Symbol: SFP插座-20PINSFP; AddInBom: yes
U13 = 贴片钽电容100uF+-20%6.3VB型: AddInBom: yes; ModelId: c87e3c47f1734e1fb3c58ebf7c04e8630819f05c4eef4c71ace90d822a990e87; ModelTransform: 145.669,102.362,0,0,0,0,0,0,0
U14 = KF2EDG3.5MM4P直针+插座: AddInBom: yes
X1 = H6OEL89CSC-SUGYLC-14.31818M: 晶振类型:贴片晶振;频率:14.31818MHz;常温频差:±20ppm;负载电容:20pF;频率稳定度:±30ppm;; Manufacturer: YXC(扬兴晶振); AddInBom: yes; ModelId: 6f569b91267b44029b8615eb5c810fba0819f05c4eef4c71ace90d822a990e87; ModelName: HC-49S_L11.4-W1.8-H3.0-LS12.7; ModelTransform: 499.999,188.976,0,0,0,0,0.0005,0,0; Normal temperature Frequency Tolerance: ±20ppm; Load Capacitance: 20pF; Frequency Stability: ±30ppm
